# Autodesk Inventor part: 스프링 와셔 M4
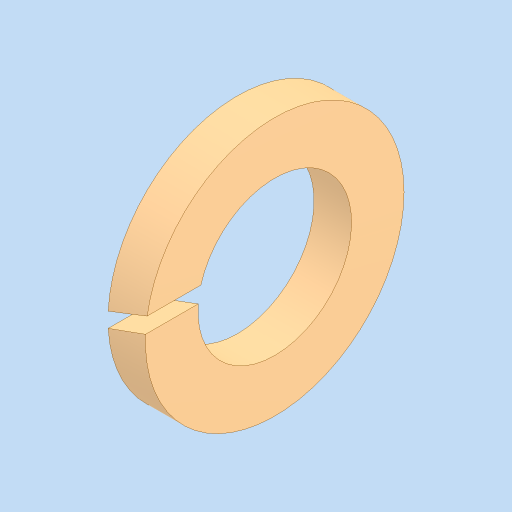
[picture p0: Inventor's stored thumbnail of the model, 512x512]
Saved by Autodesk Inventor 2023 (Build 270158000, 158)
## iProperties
Created: 2026-03
Part Number: 스프링 와셔 M4
Material: 강철, 연강
Description: 스프링 잠금 와셔
Document SubType Name: Modeling
Designer: home
Density: 7.85 g/cm^3
Appearance: 기본값
Author: jhkim
Sending System: Autodesk Inventor 2026
Preprocessor: ST-DEVELOPER v20.1
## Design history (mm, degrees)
feature "Solid1"
node "솔리드1"
